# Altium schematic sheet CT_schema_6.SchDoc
size 370 x 245 mm
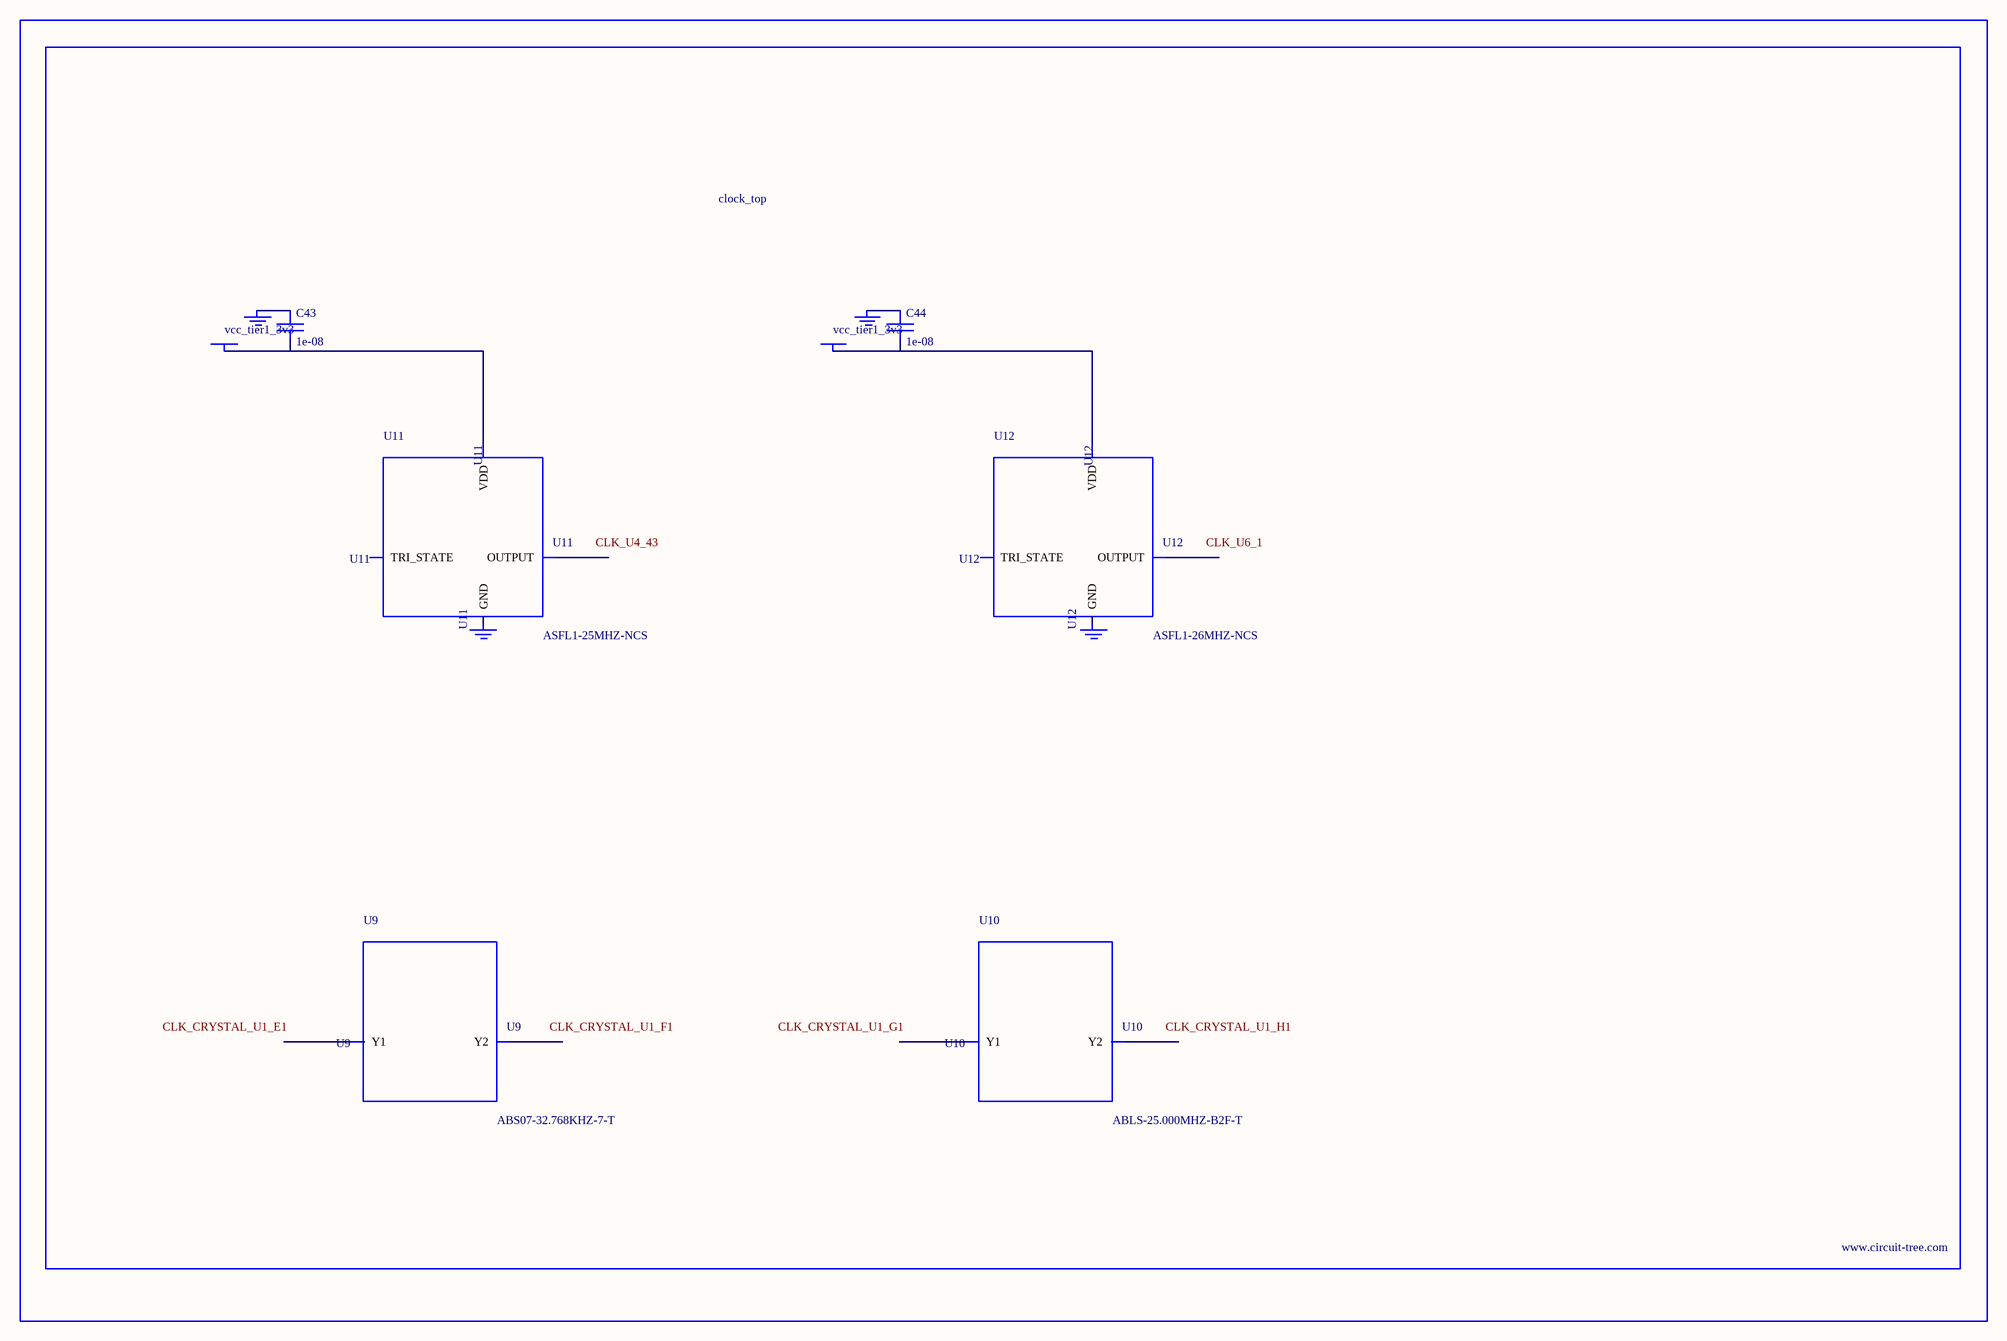
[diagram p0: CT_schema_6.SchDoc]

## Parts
BORDER5  (no value)
C43  1e-08  [C0402]
C44  1e-08  [C0402]
GND_INSTANCE_5_0  (no value)
GND_INSTANCE_5_1  (no value)
GND_INSTANCE_5_2  (no value)
GND_INSTANCE_5_3  (no value)
POWER_INSTANCE_5_0  vcc_tier1_3v3
POWER_INSTANCE_5_1  vcc_tier1_3v3
U9  ABS07-32.768KHZ-7-T  [ABS07-32.768KHZ-7-T]
U10  ABLS-25.000MHZ-B2F-T  [ABLS-25.000MHZ-B2F-T]
U11  ASFL1-25MHZ-NCS  [ASFL1]
U12  ASFL1-26MHZ-NCS  [ASFL1]

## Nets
NetC43_1: C43.1 GND_INSTANCE_5_0.0(GND)
NetC43_2: C43.2 POWER_INSTANCE_5_0.0(PWR) U11.4(VDD)
NetC44_1: C44.1 GND_INSTANCE_5_2.0(GND)
NetC44_2: C44.2 POWER_INSTANCE_5_1.0(PWR) U12.4(VDD)

Not connected (* = marked no-connect by the designer): GND_INSTANCE_5_1 0(GND); GND_INSTANCE_5_3 0(GND); U9 1(Y1) 2(Y2); U10 1(Y1) 2(Y2); U11 1(TRI_STATE) 2(GND) 3(OUTPUT); U12 1(TRI_STATE) 2(GND) 3(OUTPUT)

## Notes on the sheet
- Labels drawn without touching a wire or pin: CLK_CRYSTAL_U1_E1, CLK_CRYSTAL_U1_F1, CLK_CRYSTAL_U1_G1, CLK_CRYSTAL_U1_H1, CLK_U4_43, CLK_U6_1

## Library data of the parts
BORDER5 = BORDER_PAGE5
C43 C44 = C0402C103K3RAC
GND_INSTANCE_5_0-GND_INSTANCE_5_3 = GND
POWER_INSTANCE_5_0 POWER_INSTANCE_5_1 = PWR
